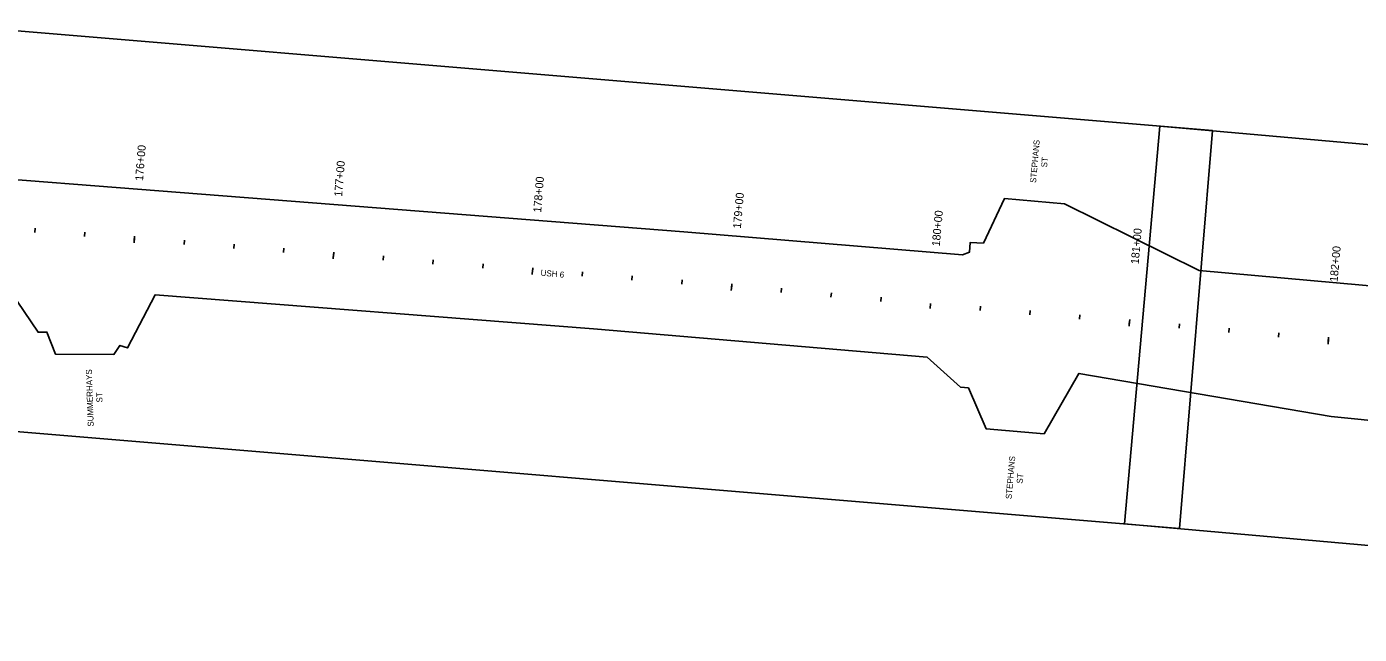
# Model space of a CAD drawing. Extents: x 20499876 to 20505320, y 7953544 to 7954108.
# Drawn here: x 20501256 to 20501924, y 7953735 to 7954040 of the extents above; entities that cross this region are included whole.
import ezdxf

# ---------------------------------------------------------------- set-up
doc = ezdxf.new("R2010")
doc.units = 0
for name, color, linetype in [('Draft_0', 7, 'Continuous'), ('Draft_7', 7, 'Continuous'), ('Drainage- Pipe', 7, 'Continuous'), ('PS_CONST', 7, 'Continuous'), ('Wall', 7, 'Continuous')]:
    doc.layers.add(name, color=color, linetype=linetype)

msp = doc.modelspace()

# ---------------------------------------------------------------- linework, layer by layer
at = {"layer": 'Draft_7'}
for p, q in [((20501260.29, 7953936.35), (20501260.46, 7953938.53)), ((20501285.21, 7953934.37), (20501285.38, 7953936.55)), ((20501310.23, 7953933.61), (20501310.03, 7953931.17)), ((20501335.05, 7953930.41), (20501335.22, 7953932.59)), ((20501359.97, 7953928.43), (20501360.14, 7953930.61)), ((20501384.89, 7953926.45), (20501385.07, 7953928.63)), ((20501409.91, 7953925.69), (20501409.72, 7953923.25)), ((20501434.74, 7953922.49), (20501434.91, 7953924.67)), ((20501459.66, 7953920.51), (20501459.83, 7953922.69)), ((20501484.58, 7953918.53), (20501484.75, 7953920.71)), ((20501509.6, 7953917.77), (20501509.4, 7953915.33)), ((20501534.42, 7953914.57), (20501534.59, 7953916.75)), ((20501559.34, 7953912.59), (20501559.52, 7953914.76)), ((20501584.26, 7953910.61), (20501584.44, 7953912.78)), ((20501609.29, 7953909.77), (20501609.07, 7953907.34)), ((20501634.08, 7953906.33), (20501634.28, 7953908.5)), ((20501658.98, 7953904.1), (20501659.18, 7953906.27)), ((20501683.88, 7953901.87), (20501684.08, 7953904.04)), ((20501708.89, 7953900.86), (20501708.67, 7953898.42)), ((20501733.68, 7953897.41), (20501733.88, 7953899.58)), ((20501758.58, 7953895.18), (20501758.78, 7953897.35)), ((20501783.48, 7953892.95), (20501783.68, 7953895.12)), ((20501808.49, 7953891.94), (20501808.27, 7953889.5)), ((20501833.28, 7953888.49), (20501833.48, 7953890.66)), ((20501858.18, 7953886.26), (20501858.38, 7953888.43)), ((20501883.08, 7953884.03), (20501883.28, 7953886.2)), ((20501908.09, 7953883.02), (20501907.88, 7953880.58))]:
    msp.add_line(p, q, dxfattribs=at)
at = {"layer": 'Drainage- Pipe'}
for points in [[(20501225.23, 7954039.5), (20501208.63, 7953840.19), (20501833.46, 7953788.16), (20501850.06, 7953987.47)], [(20501823.68, 7953989.74), (20501806.03, 7953790.52), (20502430.58, 7953735.18), (20502448.23, 7953934.4)]]:
    msp.add_lwpolyline(points, close=True, dxfattribs=at)
at = {"layer": 'PS_CONST'}
for p, q in [((20501310.13, 7953932.39), (20501310.3, 7953934.57)), ((20501409.81, 7953924.47), (20501409.99, 7953926.65)), ((20501509.5, 7953916.55), (20501509.67, 7953918.73)), ((20501609.18, 7953908.55), (20501609.37, 7953910.73)), ((20501708.89, 7953900.86), (20501708.67, 7953898.42)), ((20501808.38, 7953890.72), (20501808.58, 7953892.89)), ((20501907.98, 7953881.8), (20501908.18, 7953883.97))]:
    msp.add_line(p, q, dxfattribs=at)
at = {"layer": 'Wall'}
for points in [[(20500961.05, 7953985.49), (20501585.27, 7953936.81), (20501724.91, 7953925.27), (20501728.32, 7953926.51), (20501728.73, 7953931.44), (20501735.34, 7953931.05), (20501745.91, 7953953.5), (20501775.93, 7953950.79), (20501843.37, 7953917.33), (20502120.24, 7953892.49), (20502373.22, 7953872.83), (20502501.07, 7953863.11), (20502518.94, 7953887.24), (20502524.88, 7953886.71), (20502539.39, 7953890.66), (20502579.49, 7953887.98), (20502593.01, 7953888.5)], [(20502125.33, 7953822.5), (20501909.53, 7953844.31), (20501783.16, 7953865.85), (20501765.7, 7953835.6), (20501736.68, 7953838.13), (20501727.8, 7953858.68), (20501723.86, 7953859.03), (20501707.21, 7953873.97), (20501540.13, 7953888.22), (20501320.52, 7953905.16), (20501306.78, 7953878.61), (20501302.9, 7953879.88), (20501299.93, 7953875.35), (20501270.66, 7953875.56), (20501266.35, 7953886.51), (20501261.93, 7953886.46), (20501244.4, 7953912.4)]]:
    msp.add_lwpolyline(points, dxfattribs=at)

# ---------------------------------------------------------------- texts
at = {"layer": 'Draft_0'}
for s, rotation, p in [('STEPHANS', 85, (20501761.65, 7953961.14)), ('ST', 85, (20501767.15, 7953968.91)), ('USH 6', 355, (20501513.49, 7953914.81)), ('SUMMERHAYS', 91.87706, (20501289.82, 7953839.23)), ('ST', 91.87706, (20501294.22, 7953851.31)), ('STEPHANS', 85, (20501749.42, 7953802.8)), ('ST', 85, (20501754.91, 7953810.57))]:
    msp.add_text(s, height=3, rotation=rotation, dxfattribs=at).set_placement(p)
at = {"layer": 'Draft_7'}
for s, rotation, p in [('176+00', 85.45642, (20501314.5, 7953962.14)), ('177+00', 85.45642, (20501414.19, 7953954.22)), ('178+00', 85.45642, (20501513.87, 7953946.3)), ('179+00', 84.88337, (20501613.85, 7953938.26)), ('180+00', 84.88337, (20501713.45, 7953929.34)), ('181+00', 84.88337, (20501813.05, 7953920.42)), ('182+00', 84.88337, (20501912.66, 7953911.5))]:
    msp.add_text(s, height=4.008, rotation=rotation, dxfattribs=at).set_placement(p)
at = {"layer": 'PS_CONST'}
msp.add_text('180+00', height=4.008, rotation=84.88337, dxfattribs=at).set_placement((20501713.45, 7953929.34))

doc.saveas('drawing.dxf')
